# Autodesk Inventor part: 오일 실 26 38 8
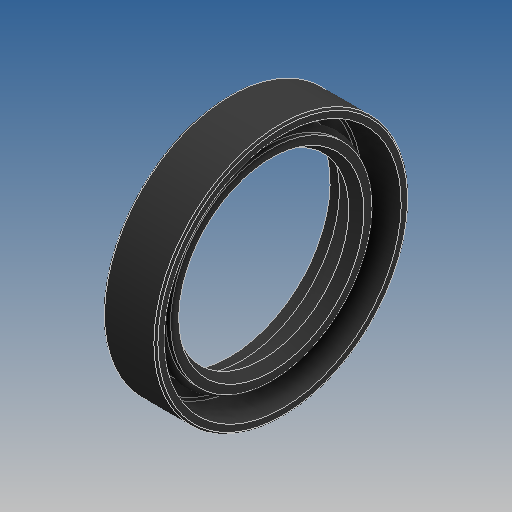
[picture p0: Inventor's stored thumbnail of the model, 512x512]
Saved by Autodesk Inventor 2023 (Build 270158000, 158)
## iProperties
Created: 2025-03
Part Number: 오일 실 26 38 8
Material: 고무
Description: 오일-실
Document SubType Name: Modeling
Designer: Admin
Density: 0.93 g/cm^3
Appearance: 기본값
Author: jhkim
Sending System: Autodesk Inventor 2025
Preprocessor: ST-DEVELOPER v20
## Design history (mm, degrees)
node "오일 실 26 38 81"
node "솔리드1"
body "Solid1"
